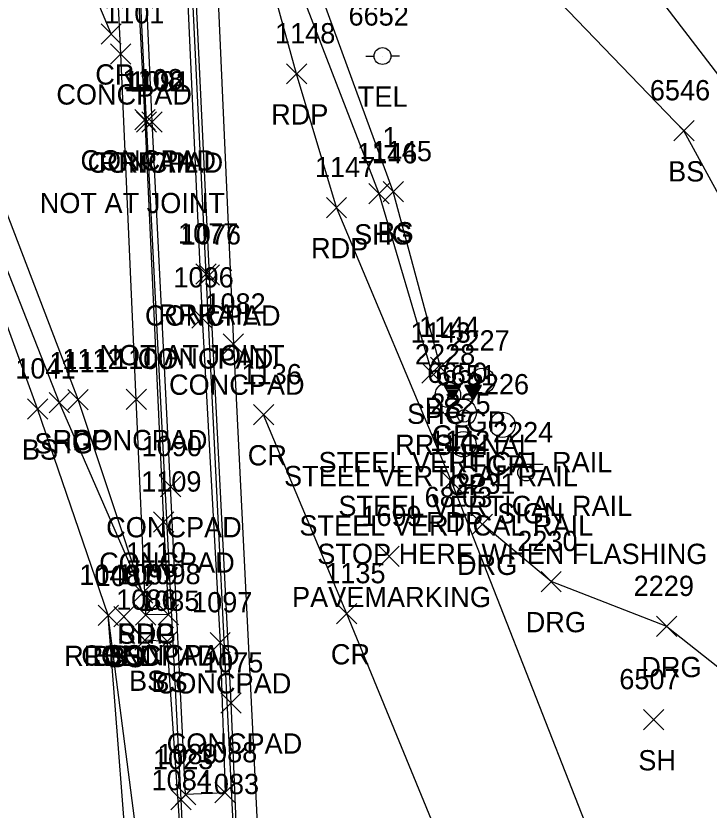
# Model space of a CAD drawing. Extents: x 1769141 to 1770817, y 735471 to 742405.
# Drawn here: x 1770160.9 to 1770229.2, y 740809.3 to 740887.6 of the extents above; entities that cross this region are included whole.
import ezdxf

# ---------------------------------------------------------------- set-up
doc = ezdxf.new("R2010")
doc.units = 0
for name, color, linetype in [('C_A', 7, 'Continuous'), ('C_C', 7, 'Continuous'), ('C_I', 7, 'Continuous'), ('CBP', 7, 'Continuous'), ('L_A', 7, 'Continuous'), ('L_I', 7, 'Continuous'), ('L_TIC', 7, 'Continuous'), ('LELB', 7, 'Continuous'), ('LS', 7, 'Continuous'), ('P_A', 7, 'Continuous'), ('P_I', 7, 'Continuous'), ('P_TIC', 7, 'Continuous'), ('PET', 7, 'Continuous'), ('PRC', 7, 'Continuous'), ('PSU', 7, 'Continuous'), ('R_A', 7, 'Continuous'), ('R_C', 7, 'Continuous'), ('R_I', 7, 'Continuous'), ('R_TIC', 7, 'Continuous'), ('RDG', 7, 'Continuous'), ('RGP', 7, 'Continuous'), ('RR', 7, 'Continuous'), ('RRB', 7, 'Continuous'), ('S_A', 7, 'Continuous'), ('S_C', 7, 'Continuous'), ('S_I', 7, 'Continuous'), ('S_TIC', 7, 'Continuous'), ('SSGN', 7, 'Continuous'), ('TCSH', 7, 'Continuous'), ('U_A', 7, 'Continuous'), ('U_C', 7, 'Continuous'), ('U_I', 7, 'Continuous'), ('UP', 7, 'Continuous')]:
    doc.layers.add(name, color=color, linetype=linetype)

msp = doc.modelspace()

# ---------------------------------------------------------------- linework, layer by layer
at = {"layer": 'CBP'}
for radius in [0.625, 0.0833]:
    msp.add_circle((1770205.05, 740848.129), radius, dxfattribs=at)
at = {"layer": 'L_TIC'}
for points in [[(1770170.207, 740882.814), (1770172.207, 740884.814)], [(1770172.207, 740882.814), (1770170.207, 740884.814)], [(1770172.586, 740876.315), (1770174.586, 740878.315)], [(1770174.586, 740876.315), (1770172.586, 740878.315)], [(1770173.289, 740876.102), (1770175.289, 740878.102)], [(1770175.289, 740876.102), (1770173.289, 740878.102)], [(1770225.756, 740875.232), (1770227.756, 740877.232)], [(1770227.756, 740875.232), (1770225.756, 740877.232)], [(1770197.081, 740869.23), (1770199.081, 740871.23)], [(1770199.081, 740869.23), (1770197.081, 740871.23)], [(1770178.949, 740861.02), (1770180.949, 740863.02)], [(1770180.949, 740861.02), (1770178.949, 740863.02)], [(1770178.23, 740856.786), (1770180.23, 740858.786)], [(1770180.23, 740856.786), (1770178.23, 740858.786)], [(1770181.321, 740854.204), (1770183.321, 740856.204)], [(1770183.321, 740854.204), (1770181.321, 740856.204)], [(1770201.748, 740851.913), (1770203.748, 740853.913)], [(1770203.748, 740851.913), (1770201.748, 740853.913)], [(1770171.741, 740848.746), (1770173.741, 740850.746)], [(1770173.741, 740848.746), (1770171.741, 740850.746)], [(1770162.01, 740847.807), (1770164.01, 740849.807)], [(1770164.01, 740847.807), (1770162.01, 740849.807)], [(1770175.123, 740840.151), (1770177.123, 740842.151)], [(1770177.123, 740840.151), (1770175.123, 740842.151)], [(1770174.431, 740836.66), (1770176.431, 740838.66)], [(1770176.431, 740836.66), (1770174.431, 740838.66)], [(1770168.979, 740827.468), (1770170.979, 740829.468)], [(1770170.979, 740827.468), (1770168.979, 740829.468)], [(1770172.666, 740827.505), (1770174.666, 740829.505)], [(1770174.666, 740827.505), (1770172.666, 740829.505)], [(1770174.91, 740827.532), (1770176.91, 740829.532)], [(1770176.91, 740827.532), (1770174.91, 740829.532)], [(1770170.509, 740827.346), (1770172.509, 740829.346)], [(1770172.509, 740827.346), (1770170.509, 740829.346)], [(1770172.58, 740825.018), (1770174.58, 740827.018)], [(1770174.58, 740825.018), (1770172.58, 740827.018)], [(1770174.788, 740824.9), (1770176.788, 740826.9)], [(1770176.788, 740824.9), (1770174.788, 740826.9)], [(1770180.013, 740824.759), (1770182.013, 740826.759)], [(1770182.013, 740824.759), (1770180.013, 740826.759)], [(1770181.09, 740818.829), (1770183.09, 740820.829)], [(1770183.09, 740818.829), (1770181.09, 740820.829)], [(1770222.769, 740817.178), (1770224.769, 740819.178)], [(1770224.769, 740817.178), (1770222.769, 740819.178)], [(1770176.601, 740809.791), (1770178.601, 740811.791)], [(1770178.601, 740809.791), (1770176.601, 740811.791)], [(1770180.497, 740809.972), (1770182.497, 740811.972)], [(1770182.497, 740809.972), (1770180.497, 740811.972)]]:
    msp.add_lwpolyline(points, dxfattribs=at)
at = {"layer": 'LELB'}
for points in [[(1770202.748, 740852.913), (1770198.081, 740870.23), (1770189.013, 740895.049), (1770187.933, 740904.335), (1770187.578, 740912.346), (1770187.376, 740919.181), (1770186.633, 740920.541), (1770186.963, 740928.353), (1770183.64, 740957.629), (1770181.485, 740987.987), (1770182.217, 741002.634), (1770183.145, 741024.654), (1770182.277, 741042.266), (1770177.798, 741053.788), (1770174.941, 741071.303), (1770172.875, 741083.308)], [(1770197.698, 740916.027), (1770212.313, 740904.986), (1770232.76, 740878.304), (1770235.612, 740872.306)], [(1770240.242, 740844.356), (1770238.589, 740848.809), (1770239.598, 740852.724), (1770226.756, 740876.232), (1770210.967, 740892.635)], [(1770175.543, 740708.348), (1770174.677, 740743.844), (1770173.121, 740779.848), (1770172.378, 740797.524), (1770169.979, 740828.468), (1770163.01, 740848.807), (1770152.862, 740876.538)], [(1770185.641, 740791.106), (1770182.385, 740800.157), (1770181.674, 740807.84), (1770177.016, 740808.228), (1770175.788, 740825.9), (1770173.58, 740826.018), (1770171.509, 740828.346)]]:
    msp.add_lwpolyline(points, dxfattribs=at)
at = {"layer": 'LS'}
for points in [[(1770175.91, 740828.532), (1770173.666, 740828.505), (1770172.741, 740849.746), (1770171.207, 740883.814), (1770169.489, 740918.486), (1770168.395, 740936.351), (1770170.611, 740936.475), (1770171.921, 740909.341), (1770173.586, 740877.315), (1770175.431, 740837.66), (1770175.91, 740828.532)], [(1770181.497, 740810.972), (1770177.601, 740810.791), (1770176.123, 740841.151), (1770174.289, 740877.102), (1770172.811, 740909.903), (1770171.911, 740927.324), (1770175.874, 740927.561), (1770177.323, 740899.59), (1770179.23, 740857.786), (1770181.013, 740825.759), (1770181.497, 740810.972)], [(1770184.958, 740801.926), (1770182.863, 740801.839), (1770182.09, 740819.829), (1770179.949, 740862.02), (1770177.219, 740918.781), (1770179.299, 740918.82), (1770180.432, 740897.898), (1770182.321, 740855.204), (1770184.958, 740801.926)]]:
    msp.add_lwpolyline(points, dxfattribs=at)
at = {"layer": 'P_TIC'}
for points in [[(1770169.261, 740884.785), (1770171.261, 740886.785)], [(1770171.261, 740884.785), (1770169.261, 740886.785)], [(1770187.55, 740880.845), (1770189.55, 740882.845)], [(1770189.55, 740880.845), (1770187.55, 740882.845)], [(1770195.692, 740869.02), (1770197.692, 740871.02)], [(1770197.692, 740869.02), (1770195.692, 740871.02)], [(1770191.486, 740867.66), (1770193.486, 740869.66)], [(1770193.486, 740867.66), (1770191.486, 740869.66)], [(1770200.911, 740851.342), (1770202.911, 740853.342)], [(1770202.911, 740851.342), (1770200.911, 740853.342)], [(1770165.998, 740848.734), (1770167.998, 740850.734)], [(1770167.998, 740848.734), (1770165.998, 740850.734)], [(1770164.15, 740848.421), (1770166.15, 740850.421)], [(1770166.15, 740848.421), (1770164.15, 740850.421)], [(1770184.3, 740847.24), (1770186.3, 740849.24)], [(1770186.3, 740847.24), (1770184.3, 740849.24)], [(1770202.823, 740840.666), (1770204.823, 740842.666)], [(1770204.823, 740840.666), (1770202.823, 740842.666)], [(1770172.361, 740829.661), (1770174.361, 740831.661)], [(1770174.361, 740829.661), (1770172.361, 740831.661)], [(1770172.361, 740829.661), (1770174.361, 740831.661)], [(1770174.361, 740829.661), (1770172.361, 740831.661)], [(1770192.497, 740827.625), (1770194.497, 740829.625)], [(1770194.497, 740827.625), (1770192.497, 740829.625)]]:
    msp.add_lwpolyline(points, dxfattribs=at)
at = {"layer": 'PET'}
for points in [[(1770173.361, 740830.661), (1770166.998, 740849.734), (1770156.441, 740877.247), (1770149.842, 740895.223), (1770143.531, 740906.327), (1770134.194, 740929.895), (1770122.879, 740955.26)], [(1770234.493, 740765.319), (1770220.538, 740799.067), (1770203.823, 740841.666), (1770192.486, 740868.66), (1770188.55, 740881.845), (1770185.29, 740893.661), (1770179.48, 740917.38)]]:
    msp.add_lwpolyline(points, dxfattribs=at)
at = {"layer": 'PRC'}
for points in [[(1770170.261, 740885.785), (1770157.552, 740916.053), (1770142.593, 740952.596)], [(1770221.591, 740759.673), (1770207.239, 740795.182), (1770193.497, 740828.625), (1770185.3, 740848.24)]]:
    msp.add_lwpolyline(points, dxfattribs=at)
at = {"layer": 'PSU'}
for points in [[(1770201.911, 740852.342), (1770196.692, 740870.02), (1770187.317, 740894.271), (1770183.644, 740911.936), (1770179.48, 740917.38)], [(1770173.361, 740830.661), (1770165.15, 740849.421), (1770154.482, 740876.527), (1770145.978, 740894.509), (1770140.089, 740904.164)]]:
    msp.add_lwpolyline(points, dxfattribs=at)
at = {"layer": 'R_TIC'}
for points in [[(1770172.744, 740876.111), (1770174.744, 740878.111)], [(1770174.744, 740876.111), (1770172.744, 740878.111)], [(1770178.628, 740861.115), (1770180.628, 740863.115)], [(1770180.628, 740861.115), (1770178.628, 740863.115)], [(1770205.885, 740836.446), (1770207.885, 740838.446)], [(1770207.885, 740836.446), (1770205.885, 740838.446)], [(1770212.661, 740830.797), (1770214.661, 740832.797)], [(1770214.661, 740830.797), (1770212.661, 740832.797)], [(1770168.979, 740827.468), (1770170.979, 740829.468)], [(1770170.979, 740827.468), (1770168.979, 740829.468)], [(1770224.064, 740826.369), (1770226.064, 740828.369)], [(1770226.064, 740826.369), (1770224.064, 740828.369)], [(1770176.157, 740809.299), (1770178.157, 740811.299)], [(1770178.157, 740809.299), (1770176.157, 740811.299)]]:
    msp.add_lwpolyline(points, dxfattribs=at)
at = {"layer": 'RDG'}
for points in [[(1770225.064, 740827.369), (1770213.661, 740831.797), (1770206.885, 740837.446)], [(1770225.064, 740827.369), (1770243.609, 740812.701)]]:
    msp.add_lwpolyline(points, dxfattribs=at)
at = {"layer": 'RGP'}
for p, q in [((1770206.883, 740851.571), (1770206.883, 740851.571)), ((1770203.482, 740850.195), (1770203.482, 740850.195)), ((1770208.847, 740847.251), (1770208.847, 740847.251)), ((1770204.998, 740845.329), (1770204.998, 740845.329))]:
    msp.add_line(p, q, dxfattribs=at)
for centre, radius in [((1770206.883, 740851.571), 1.25), ((1770203.482, 740850.195), 1.25), ((1770206.883, 740851.571), 0.0833), ((1770203.482, 740850.195), 0.0833), ((1770208.847, 740847.251), 1.25), ((1770208.847, 740847.251), 0.0833), ((1770204.998, 740845.329), 1.25), ((1770204.998, 740845.329), 0.0833)]:
    msp.add_circle(centre, radius, dxfattribs=at)
at = {"layer": 'RR'}
for points in [[(1770197.753, 740390.494), (1770195.855, 740429.491), (1770193.917, 740468.481), (1770191.987, 740507.454), (1770190.016, 740546.417), (1770188.175, 740585.45), (1770186.345, 740624.52), (1770184.351, 740663.534), (1770182.414, 740702.58), (1770181.022, 740730.449), (1770179.246, 740766.268), (1770177.157, 740810.299), (1770173.744, 740877.111), (1770171.322, 740927.707), (1770169.445, 740967.981), (1770167.613, 741006.359), (1770166.537, 741027.4), (1770165.653, 741046.208), (1770163.837, 741084.651), (1770161.662, 741123.764), (1770160.41, 741153.194), (1770158.416, 741192.158), (1770156.873, 741228.018)], [(1770203.658, 740370.746), (1770201.768, 740409.672), (1770199.783, 740448.72), (1770197.896, 740487.783), (1770195.957, 740526.733), (1770194.091, 740565.766), (1770192.139, 740604.842), (1770190.284, 740643.849), (1770188.287, 740682.87), (1770186.409, 740721.831), (1770184.146, 740769.997), (1770182.623, 740801.289), (1770179.628, 740862.115), (1770176.856, 740918.905), (1770174.1, 740971.708), (1770172.224, 741013.506), (1770171.361, 741030.469), (1770170.329, 741051.221), (1770168.957, 741081.093), (1770166.986, 741119.982), (1770165.661, 741147.286), (1770164.69, 741163.317), (1770164.281, 741173.164), (1770162.436, 741212.293)]]:
    msp.add_lwpolyline(points, dxfattribs=at)
at = {"layer": 'RRB'}
msp.add_lwpolyline([(1770178.785, 740708.427), (1770177.251, 740744.065), (1770175.209, 740779.841), (1770173.847, 740798.555), (1770169.979, 740828.468)], dxfattribs=at)
at = {"layer": 'S_TIC'}
for points in [[(1770196.684, 740833.27), (1770198.684, 740835.27)], [(1770198.684, 740833.27), (1770196.684, 740835.27)]]:
    msp.add_lwpolyline(points, dxfattribs=at)
at = {"layer": 'SSGN'}
for p, q in [((1770209.553, 740843.377), (1770212.886, 740843.377)), ((1770211.2, 740842.544), (1770211.2, 740842.544))]:
    msp.add_line(p, q, dxfattribs=at)
msp.add_circle((1770211.2, 740842.544), 0.833, dxfattribs=at)
at = {"layer": 'TCSH'}
for p, q in [((1770204.766, 740851.12), (1770203.099, 740851.12)), ((1770203.099, 740851.12), (1770203.869, 740849.786)), ((1770203.996, 740849.786), (1770204.766, 740851.12)), ((1770206.8, 740851.12), (1770205.134, 740851.12)), ((1770205.134, 740851.12), (1770205.903, 740849.786)), ((1770206.03, 740849.786), (1770206.8, 740851.12)), ((1770206.03, 740849.786), (1770203.869, 740849.786)), ((1770204.95, 740848.453), (1770204.95, 740848.453))]:
    msp.add_line(p, q, dxfattribs=at)
for points in [[(1770203.143, 740851.043), (1770204.721, 740851.043)], [(1770203.22, 740850.91), (1770204.644, 740850.91)], [(1770203.297, 740850.777), (1770204.568, 740850.777)], [(1770203.374, 740850.643), (1770204.491, 740850.643)], [(1770203.451, 740850.51), (1770204.414, 740850.51)], [(1770205.161, 740851.072), (1770206.772, 740851.072)], [(1770205.238, 740850.938), (1770206.695, 740850.938)], [(1770205.315, 740850.805), (1770206.618, 740850.805)], [(1770205.392, 740850.672), (1770206.541, 740850.672)], [(1770205.469, 740850.538), (1770206.464, 740850.538)], [(1770203.528, 740850.377), (1770204.337, 740850.377)], [(1770203.605, 740850.243), (1770204.26, 740850.243)], [(1770203.682, 740850.11), (1770204.183, 740850.11)], [(1770203.759, 740849.977), (1770204.106, 740849.977)], [(1770203.836, 740849.843), (1770204.029, 740849.843)], [(1770205.546, 740850.405), (1770206.388, 740850.405)], [(1770205.623, 740850.272), (1770206.311, 740850.272)], [(1770205.7, 740850.138), (1770206.234, 740850.138)], [(1770205.777, 740850.005), (1770206.157, 740850.005)], [(1770205.854, 740849.872), (1770206.08, 740849.872)]]:
    msp.add_lwpolyline(points, dxfattribs=at)
msp.add_circle((1770204.95, 740848.453), 1.333, dxfattribs=at)
at = {"layer": 'UP'}
for p, q in [((1770195.368, 740883.594), (1770196.194, 740883.593)), ((1770197.028, 740883.599), (1770197.028, 740883.599)), ((1770198.694, 740883.599), (1770197.861, 740883.599)), ((1770197.861, 740883.599), (1770197.861, 740883.599)), ((1770198.694, 740883.599), (1770198.694, 740883.599))]:
    msp.add_line(p, q, dxfattribs=at)
msp.add_circle((1770197.028, 740883.599), 0.833, dxfattribs=at)

# ---------------------------------------------------------------- texts
at = {"layer": 'C_A'}
msp.add_text('TIE', height=2, dxfattribs=at).set_placement((1770203.129, 740843.129))
at = {"layer": 'C_C'}
msp.add_text('68.03', height=2, dxfattribs=at).set_placement((1770201.176, 740839.129))
at = {"layer": 'C_I'}
msp.add_text('6651', height=2, dxfattribs=at).set_placement((1770202.263, 740851.129))
at = {"layer": 'L_A'}
for s, p in [('CONCPAD', (1770164.853, 740878.814)), ('CONCPAD', (1770167.232, 740872.315)), ('CONCPAD', (1770167.935, 740872.102)), ('BS', (1770225.197, 740871.232)), ('BS', (1770196.522, 740865.23)), ('CONCPAD', (1770173.595, 740857.02)), ('CONCPAD', (1770172.876, 740852.786)), ('CONCPAD', (1770175.967, 740850.204)), ('BS', (1770201.189, 740847.913)), ('CONCPAD', (1770166.387, 740844.746)), ('BS', (1770161.451, 740843.807)), ('CONCPAD', (1770169.769, 740836.151)), ('CONCPAD', (1770169.077, 740832.66)), ('CONCPAD', (1770167.312, 740823.505)), ('BS', (1770168.42, 740823.468)), ('CONCPAD', (1770169.556, 740823.532)), ('BS', (1770169.95, 740823.346)), ('BS', (1770172.021, 740821.018)), ('BS', (1770174.229, 740820.9)), ('CONCPAD', (1770174.658, 740820.759)), ('CONCPAD', (1770175.736, 740814.829)), ('SH', (1770222.257, 740813.178))]:
    msp.add_text(s, height=2, dxfattribs=at).set_placement(p)
at = {"layer": 'L_I'}
for s, p in [('1101', (1770169.569, 740886.814)), ('1108', (1770171.381, 740880.315)), ('1091', (1770172.085, 740880.102)), ('6546', (1770223.394, 740879.232)), ('1145', (1770195.955, 740873.23)), ('1076', (1770177.122, 740865.02)), ('1096', (1770176.403, 740860.786)), ('1082', (1770179.55, 740858.204)), ('1144', (1770200.622, 740855.913)), ('1100', (1770170.45, 740852.746)), ('1041', (1770160.806, 740851.807)), ('1090', (1770173.265, 740844.151)), ('1109', (1770173.219, 740840.66)), ('1040', (1770167.121, 740831.468)), ('1087', (1770168.737, 740831.346)), ('1099', (1770170.887, 740831.505)), ('1098', (1770173.139, 740831.532)), ('1086', (1770170.754, 740829.018)), ('1085', (1770173.016, 740828.9)), ('1097', (1770178.241, 740828.759)), ('1075', (1770179.319, 740822.829)), ('6507', (1770220.383, 740821.178)), ('1089', (1770174.822, 740813.791)), ('1088', (1770178.725, 740813.972)), ('1084', (1770174.244, 740811.228)), ('1083', (1770178.903, 740810.84))]:
    msp.add_text(s, height=2, dxfattribs=at).set_placement(p)
at = {"layer": 'P_A'}
for s, p in [('CR', (1770168.694, 740880.785)), ('RDP', (1770186.038, 740876.845)), ('SHG', (1770194.227, 740865.02)), ('RDP', (1770189.974, 740863.66)), ('SHG', (1770199.447, 740847.342)), ('RDP', (1770164.486, 740844.734)), ('SHG', (1770162.685, 740844.421)), ('CR', (1770183.733, 740843.24)), ('RDP', (1770201.312, 740836.666)), ('SHG', (1770170.896, 740825.661)), ('RDP', (1770170.849, 740825.661)), ('CR', (1770191.931, 740823.625))]:
    msp.add_text(s, height=2, dxfattribs=at).set_placement(p)
at = {"layer": 'P_I'}
for s, p in [('1148', (1770186.424, 740884.845)), ('1146', (1770194.511, 740873.02)), ('1147', (1770190.36, 740871.66)), ('1143', (1770199.786, 740855.342)), ('1112', (1770165.44, 740852.734)), ('1111', (1770164.158, 740852.421)), ('1136', (1770183.119, 740851.24)), ('1142', (1770201.698, 740844.666)), ('1110', (1770171.715, 740833.661)), ('1110', (1770171.715, 740833.661)), ('1135', (1770191.372, 740831.625))]:
    msp.add_text(s, height=2, dxfattribs=at).set_placement(p)
at = {"layer": 'R_A'}
for s, p in [('RRRAIL', (1770169.036, 740872.111)), ('RRRAIL', (1770174.92, 740857.115)), ('GP', (1770205.316, 740846.571)), ('GP', (1770201.915, 740845.195)), ('RRSIGNAL', (1770198.276, 740844.275)), ('GP', (1770207.28, 740842.251)), ('GP', (1770203.431, 740840.329)), ('DRG', (1770204.373, 740832.446)), ('DRG', (1770211.149, 740826.797)), ('RRBED', (1770165.625, 740823.468)), ('DRG', (1770222.552, 740822.369))]:
    msp.add_text(s, height=2, dxfattribs=at).set_placement(p)
at = {"layer": 'R_C'}
for s, p in [('NOT AT JOINT', (1770163.217, 740868.111)), ('NOT AT JOINT', (1770169.101, 740853.115)), ('STEEL VERTICAL RAIL', (1770190.711, 740842.571)), ('STEEL VERTICAL RAIL', (1770187.31, 740841.195)), ('STEEL VERTICAL RAIL', (1770192.674, 740838.251)), ('STEEL VERTICAL RAIL', (1770188.826, 740836.329))]:
    msp.add_text(s, height=2, dxfattribs=at).set_placement(p)
at = {"layer": 'R_I'}
for s, p in [('1102', (1770171.54, 740880.111)), ('1077', (1770176.857, 740865.115)), ('2227', (1770203.623, 740854.571)), ('2228', (1770200.223, 740853.195)), ('6650', (1770201.434, 740851.375)), ('2226', (1770205.532, 740850.251)), ('2225', (1770201.739, 740848.329)), ('2231', (1770204.192, 740840.446)), ('2230', (1770210.315, 740834.797)), ('1040', (1770167.121, 740831.468)), ('2229', (1770221.797, 740830.369)), ('1023', (1770174.385, 740813.299))]:
    msp.add_text(s, height=2, dxfattribs=at).set_placement(p)
at = {"layer": 'S_A'}
for s, p in [('SIGN', (1770208.338, 740837.523)), ('PAVEMARKING', (1770188.101, 740829.27))]:
    msp.add_text(s, height=2, dxfattribs=at).set_placement(p)
at = {"layer": 'S_C'}
msp.add_text('STOP HERE WHEN FLASHING', height=2, dxfattribs=at).set_placement((1770190.59, 740833.523))
at = {"layer": 'S_I'}
for s, p in [('2224', (1770207.92, 740845.523)), ('1699', (1770194.936, 740837.27))]:
    msp.add_text(s, height=2, dxfattribs=at).set_placement(p)
at = {"layer": 'U_A'}
msp.add_text('TEL', height=2, dxfattribs=at).set_placement((1770194.587, 740878.599))
at = {"layer": 'U_C'}
msp.add_text('1', height=2, dxfattribs=at).set_placement((1770197.028, 740874.599))
at = {"layer": 'U_I'}
msp.add_text('6652', height=2, dxfattribs=at).set_placement((1770193.673, 740886.599))

doc.saveas('drawing.dxf')
